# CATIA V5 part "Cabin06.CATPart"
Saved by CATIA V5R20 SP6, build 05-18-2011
Part number: Cabin06
Bounding box of the stored display mesh (mm): x 578.019 to 721.019, y 0 to 20, z 395 to 635
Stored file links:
  E:\#01 CATIA Lecture Materials\#06 DMU\#01 DMU KIN Page01 EX01\#01 CATPart\Cabin06.CATPart
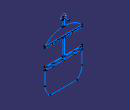
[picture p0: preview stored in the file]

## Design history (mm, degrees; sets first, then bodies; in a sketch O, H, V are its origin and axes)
Set1
  DatumCurve1 "Curve.1 ( *CRV20 - wsp *MASTER -  )"
  DatumCurve2 "Curve.2 ( *CRV21 - wsp *MASTER -  )"
  DatumCurve3 "Curve.3 ( *CRV22 - wsp *MASTER -  )"
  DatumCurve4 "Curve.4 ( *CRV23 - wsp *MASTER -  )"
  DatumCurve5 "Curve.5 ( *CRV24 - wsp *MASTER -  )"
  DatumCurve6 "Curve.6 ( *CRV25 - wsp *MASTER -  )"
  DatumCurve7 "Curve.7 ( *CRV26 - wsp *MASTER -  )"
  DatumCurve8 "Curve.8 ( *CRV27 - wsp *MASTER -  )"
  DatumCurve9 "Curve.9 ( *CRV28 - wsp *MASTER -  )"
  DatumCurve10 "Curve.10 ( *CRV29 - wsp *MASTER -  )"
  DatumCurve11 "Curve.11 ( *CRV30 - wsp *MASTER -  )"
  DatumCurve12 "Curve.12 ( *CRV31 - wsp *MASTER -  )"
  DatumCurve13 "Curve.13 ( *CRV32 - wsp *MASTER -  )"
  DatumCurve14 "Curve.14 ( *CRV33 - wsp *MASTER -  )"
  DatumCurve15 "Curve.15 ( *CRV34 - wsp *MASTER -  )"
  DatumCurve16 "Curve.16 ( *CRV35 - wsp *MASTER -  )"
  DatumCurve17 "Curve.17 ( *CRV36 - wsp *MASTER -  )"
  Line1 "Line.1 ( *LN53 - wsp *MASTER -  )": stored without definition
  Line2 "Line.2 ( *LN54 - wsp *MASTER -  )": stored without definition
  Line3 "Line.3 ( *LN55 - wsp *MASTER -  )": stored without definition
  Line4 "Line.4 ( *LN56 - wsp *MASTER -  )": stored without definition
  Line5 "Line.5 ( *LN57 - wsp *MASTER -  )": stored without definition
  Line6 "Line.6 ( *LN58 - wsp *MASTER -  )": stored without definition
  Line7 "Line.7 ( *LN59 - wsp *MASTER -  )": stored without definition
  Line8 "Line.8 ( *LN60 - wsp *MASTER -  )": stored without definition
  Line9 "Line.9 ( *LN61 - wsp *MASTER -  )": stored without definition
  Line10 "Line.10 ( *LN62 - wsp *MASTER -  )": stored without definition
  Line11 "Line.11 ( *LN63 - wsp *MASTER -  )": stored without definition
  Line12 "Line.12 ( *LN64 - wsp *MASTER -  )": stored without definition
  Line13 "Line.13 ( *LN65 - wsp *MASTER -  )": stored without definition
  Line14 "Line.14 ( *LN66 - wsp *MASTER -  )": stored without definition
  Line15 "Line.15 ( *LN67 - wsp *MASTER -  )": stored without definition
  Line16 "Line.16 ( *LN68 - wsp *MASTER -  )": stored without definition
  Line17 "Line.17 ( *LN69 - wsp *MASTER -  )": stored without definition
  Line18 "Line.18 ( *LN70 - wsp *MASTER -  )": stored without definition
  Line19 "Line.19 ( *LN71 - wsp *MASTER -  )": stored without definition
  Line20 "Line.20 ( *LN72 - wsp *MASTER -  )": stored without definition
  Line21 "Line.21 ( *LN73 - wsp *MASTER -  )": stored without definition
  Line22 "Line.22 ( *LN74 - wsp *MASTER -  )": stored without definition
  Line23 "Line.23 ( *LN75 - wsp *MASTER -  )": stored without definition
  Line24 "Line.24 ( *LN76 - wsp *MASTER -  )": stored without definition
  Line25 "Line.25 ( *LN77 - wsp *MASTER -  )": stored without definition
  Line26 "Line.26 ( *LN78 - wsp *MASTER -  )": stored without definition
  Line27 "Line.27 ( *LN79 - wsp *MASTER -  )": stored without definition
  Line28 "Line.28 ( *LN80 - wsp *MASTER -  )": stored without definition
  Line29 "Line.29 ( *LN81 - wsp *MASTER -  )": stored without definition
  Line30 "Line.30 ( *LN82 - wsp *MASTER -  )": stored without definition
  Line31: stored without definition
Body1 (main body)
